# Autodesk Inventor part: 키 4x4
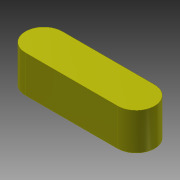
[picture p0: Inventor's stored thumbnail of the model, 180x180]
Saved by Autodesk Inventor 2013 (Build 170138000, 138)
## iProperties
Created: 2016-04
Part Number: 키 4x4
Document SubType Name: Modeling
Designer: mdu
Density: 7.86 g/cm^3
Mass: 1.65269 g
Surface Area: 2.35398 cm^2
Volume: 0.210265 cm^3
Material: 강철, 연강
Author: mdu
Revision Number: 1
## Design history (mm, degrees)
sketch "스케치1"
  geometry: L1 (-5, -2)-(5, -2); L2 (5, 2)-(-5, 2); A1 r 2 centre (5, 0) between (5, -2) and (5, 2); A2 r 2 centre (-5, 0) between (-5, 2) and (-5, -2); 2 further points
  constraints: 4 end point, 4 point on circle, 4 tangent, 2 centre point, 1 horizontal, 1 horizontal alignment, 1 midpoint, 1 parallel, 1 vertical alignment
  dimensions: "d0" = 4 distance between parallel lines of L1 L2; "d1" = 14 dimension on A1 A2
extrude "돌출1" new body sketch "스케치1" stored distance "d2" = 4; taper "d3" = 0 deg
chamfer "모따기1" distance "d4" = 0.5; stored, may be unused: second distance "d5" = 2, angle "d6" = 45 deg
node "솔리드1"
other parameters: "d0" = 4
